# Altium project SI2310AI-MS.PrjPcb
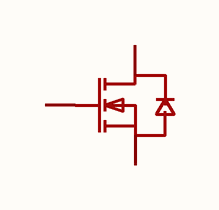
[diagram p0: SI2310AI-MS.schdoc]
1 sheet, 1 parts. Net scope: global (net labels, ports and power ports of the same name join across sheets).

## Sheet SI2310AI-MS.schdoc
size 127 x 101 mm

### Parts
Q?  si2310ai-ms  [SOT-23-3_L3.0-W1.6-P1.90-LS2.8-BR]  (value not drawn)

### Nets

Not connected (* = marked no-connect by the designer): Q? 1(G) 2(S) 3(D)

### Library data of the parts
Q? = si2310ai-ms: 数量:1个N沟道;漏源电压(Vdss):60V;连续漏极电流(Id):3A;导通电阻(RDS(on)):66mΩ@10V;耗散功率(Pd):1.7W;阈值电压(Vgs(th)):1.3V;; Manufacturer: MSKSEMI(美森科); AddInBom: yes; ModelId: 9c001725612240e7be81cfaae32ec359; ModelTransform: 114.173,116.535,0,0,0,0,0,0,0; Number: 1个N沟道; Drain to Source Voltage: 60V; Current - Continuous Drain(Id): 3A; Pd - Power Dissipation: 1.7W; Gate Threshold Voltage (Vgs(th)): 1.3V; Gate Charge(Qg): 7.5nC@4.5V; Input Capacitance(Ciss): 510pF; Reverse Transfer Capacitance (Crss@Vds): 26pF; Type: N沟道; Output Capacitance(Coss): 34pF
